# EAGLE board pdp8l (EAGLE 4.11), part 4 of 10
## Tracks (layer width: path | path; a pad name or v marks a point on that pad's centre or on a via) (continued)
INT_SKIP_EN\  (via drill 0.61) (continued)
  Top 0.203: v283.26,84.38 282.85,84.78 282.85,116.08 282.45,116.48 282.45,154.69 286.51,158.75 286.51,160.78 286.11,161.19 286.11,170.94 v286.51,171.35 | v270.26,187.6 270.26,205.08 271.07,205.89 v271.07,218.49 | v281.63,222.96 281.63,224.99 A14.T2
  Route2 0.203: v329.18,256.29 328.78,256.29 316.59,244.09 316.59,243.69 315.37,242.47 314.96,242.47 297.49,224.99 v297.49,224.59
  Route15 0.203: v270.26,187.6 v286.51,171.35 | v329.18,256.29 v356.41,229.06
  Bottom 0.203: v283.26,84.38 287.73,84.38 290.98,81.13 317.81,81.13 318.62,81.94 C11.V2 | v271.07,218.49 276.35,223.77 280.82,223.77 v281.63,222.96 | v356.41,229.06 359.66,229.06 A08.S2 | v297.49,224.59 297.08,224.18 284.07,224.18 283.26,224.99 281.63,224.99 A14.T2
INT_STROBE  (via drill 0.61)
  Top 0.203: v432.41,85.19 432,84.78 432,81.94 432.82,81.13 432.82,69.75 434.85,67.72 434.85,56.74 432,53.9 432,49.84 435.25,46.58 435.25,38.05 437.69,35.61 437.69,27.48 439.32,25.86 D02.R1
  Route2 0.203: C14.P2 284.48,99.01 284.48,100.63 293.01,109.17 294.64,109.17 296.27,110.79 C13.K2 297.49,111.61 297.49,116.08 298.3,116.89 298.3,120.95 302.36,125.02 306.43,125.02 319.84,138.43 319.84,138.84 328.78,147.78 328.78,148.59 333.25,153.06 333.25,153.47 347.88,168.1 v347.88,168.5
  Route15 0.203: v332.44,183.95 v347.88,168.5 371.04,145.34 373.48,145.34 397.87,120.95 401.12,120.95 C05.F1 401.93,120.14 403.15,118.92 403.15,115.67 404.37,114.45 404.77,114.45 432.41,86.82 v432.41,85.19
  Bottom 0.203: v332.44,183.95 329.18,183.95 B11.H1
INT_SYNC  (via drill 0.61)
  Top 0.203: v296.67,127.86 296.67,124.61 C13.E2
  Route2 0.203: v296.67,127.86 304.39,135.59 304.39,136.4 316.18,148.18 316.18,149 323.09,155.91 323.09,157.94 323.49,158.34 323.49,163.63 323.9,164.03 323.9,164.85 326.75,167.69 326.75,169.72 327.96,170.94 B11.M1
IO_ENABLE  (via drill 0.61)
  Top 0.203: v335.69,55.93 336.09,56.34 336.09,81.13 335.69,81.53 v335.69,83.57 | v304.8,177.04 304.39,176.63 304.39,172.97 303.58,172.16 B13.M1 | AB07.BL2 369.82,175.41 368.61,176.63 368.61,220.12 368.2,220.52 368.2,226.62 366.98,227.84 A08.S1 366.57,229.06 366.57,232.31 365.35,233.53 365.35,248.56 363.73,248.56 362.1,250.19 v362.1,281.89 | v303.99,281.48 298.3,275.79 298.3,251.41 294.23,251.41 A13.J2 | v284.48,115.27 282.85,116.89 282.85,148.59 v288.54,154.28
  Route2 0.203: v288.54,154.28 288.54,154.69 301.55,167.69 301.55,169.72 302.77,170.94 B13.M1
  Route15 0.203: v335.69,55.93 344.22,47.4 344.22,44.96 D09.J2 | v34.14,274.98 23.16,264.01 21.13,264.01 A35.D1 | v284.48,115.27 302.77,96.98 302.77,94.54 309.27,88.04 309.27,86.41 C12.U2
  Bottom 0.203: v335.69,83.57 334.87,84.38 315.37,84.38 314.55,85.19 310.08,85.19 C12.U2 | 419.4,175.82 409.25,175.82 408.43,175.01 AB04.BL2 407.21,174.6 405.18,174.6 403.96,175.82 396.65,175.82 395.83,175.01 AB05.BL2 394.61,175.01 390.55,175.01 389.74,175.82 384.05,175.82 383.24,175.01 AB06.BL2 382.02,175.01 377.95,175.01 377.14,175.82 373.89,175.82 373.07,175.01 370.64,175.01 AB07.BL2 369.42,175.01 365.35,175.01 361.29,179.07 345.44,179.07 343,176.63 305.21,176.63 v304.8,177.04 | 419.4,175.82 420.22,175.01 AB03.BL2 | 419.4,175.82 432,175.82 432.82,175.01 AB02.BL2 | 304.8,282.3 v303.99,281.48 | 304.8,282.3 361.7,282.3 v362.1,281.89 | v34.14,274.98 36.98,277.83 147.52,277.83 149.56,279.86 167.84,279.86 169.06,281.08 238.96,281.08 239.78,280.26 269.85,280.26 271.07,281.48 275.54,281.48 275.95,281.08 287.32,281.08 288.54,282.3 304.8,282.3
IO_END\  (via drill 0.61)
  Top 0.203: C05.K1 404.37,111.61 403.56,112.42 403.56,118.52 403.96,118.92 403.96,122.99 404.37,123.39 C05.E1 | v436.88,31.95 436.88,29.11 D02.P2
  Route2 0.203: v436.88,31.95 436.88,33.17 440.94,37.24 440.94,49.02 v452.73,60.81
  Route15 0.203: v452.73,60.81 452.32,60.4 451.51,61.21 451.51,62.43 451.1,62.84 451.1,66.9 449.07,68.94 448.67,68.94 445.01,72.59 445.01,81.53 422.66,103.89 422.66,104.29 422.25,104.7 421.44,104.7 406.81,119.33 406.81,121.77 405.18,123.39 C05.E1
IO_ON  (via drill 0.61)
  Top 0.203: D04.N2 407.62,32.36 406.81,33.17 406.81,42.93 407.62,43.74 D04.J2 407.62,44.96 407.62,47.4 406.81,48.21 406.81,55.12 | 406.81,55.12 408.03,56.34 D04.D2 | v403.56,107.95 406.4,107.95 406.4,73.41 405.99,73 405.99,72.19 407.21,70.97 407.21,66.09 406.81,65.68 406.81,55.12
  Bottom 0.203: v403.56,107.95 402.34,106.73 390.96,106.73 389.74,107.95 C06.L1
IO_PC_ENABLE\  (via drill 0.61)
  Route2 0.203: v154.84,129.9 162.97,138.02 165.41,138.02 v249.12,221.74
  Bottom 0.203: v154.84,129.9 153.62,128.68 111.35,128.68 110.13,127.46 C28.D1 | v249.12,221.74 251.16,223.77 265.38,223.77 265.79,224.18 281.63,224.18 283.26,222.56 283.67,222.56 A14.U2 284.89,222.15 286.11,220.93 358.44,220.93 359.66,222.15 A08.U2
IO_RECYCLE\
  Top 0.203: C05.P1 404.77,99.01 404.77,102.67 405.99,103.89 405.99,107.14 405.59,107.54 404.37,107.54 403.56,106.73 398.68,106.73 398.68,110.39 C05.K2
IO_ROT\  (via drill 0.61)
  Top 0.203: v371.86,40.08 377.95,40.08 377.95,63.25 381.2,66.5 381.2,105.92 382.42,107.14 C06.L2 382.42,108.76 381.2,109.98 381.2,121.36 381.61,121.77 381.61,125.42 382.42,126.24 C06.D2
  Route2 0.203: C06.B1 388.52,132.74 388.52,131.12 386.08,128.68 384.45,128.68 383.24,127.46 C06.D2
  Bottom 0.203: v371.86,40.08 363.73,40.08 363.73,43.74 D08.J1
IO_SKIP  (via drill 0.61)
  Route2 0.203: v74.78,276.2 46.74,248.16 46.74,244.91 A33.L1
  Route15 0.203: v233.27,277.01 245.06,265.23 271.07,265.23 286.92,249.38 295.86,249.38 297.08,248.16 A13.K2
  Bottom 0.203: v74.78,276.2 154.03,276.2 155.65,277.83 173.94,277.83 175.16,279.04 221.49,279.04 222.71,277.83 232.46,277.83 v233.27,277.01
IO_START\  (via drill 0.61)
  Top 0.203: 396.65,109.58 396.65,96.57 v397.46,95.76 | 396.65,109.58 396.65,114.86 395.43,116.08 395.43,120.14 C05.F2 | 396.65,109.58 v396.24,109.58
  Bottom 0.203: v397.46,95.76 401.12,95.76 C05.R1 | v396.24,109.58 415.75,109.58 416.97,110.79 C04.K1
IO_STROBE  (via drill 0.61)
  Top 0.203: v306.83,85.19 306.83,88.44 C12.T2 | v336.5,81.94 338.94,79.5 v338.94,73.41 | v391.36,107.54 390.96,107.95 390.96,112.01 391.77,112.83 391.77,116.89 C06.H1 | v367.39,83.57 367.79,83.16 367.79,69.75 365.35,67.31 365.35,53.09 363.73,51.46 D08.F1
  Route2 0.203: v278.79,145.75 279.6,146.56 279.6,149.81 289.76,159.97 289.76,162 299.52,171.75 299.52,174.19 B13.L1 | v391.36,107.54 v367.39,83.57
  Route15 0.203: D08.F1 362.92,51.05 361.29,52.68 359.66,52.68 v338.94,73.41 338.53,73.41 338.12,73.81 336.91,73.81 332.44,78.28 332.44,79.1 323.9,87.63 323.9,90.88 323.49,91.29 323.49,92.51 322.68,93.32 322.27,93.32 320.24,95.35 320.24,96.16 312.93,103.48 312.93,105.1 304.39,113.64 303.99,113.64 301.14,116.48 300.33,116.48 294.23,122.58 289.76,122.58 288.54,123.8 288.54,127.86 284.48,131.93 284.48,132.74 278.79,138.43 v278.79,145.75
  Bottom 0.203: C06.H1 392.58,117.3 397.87,117.3 C05.H2 399.08,117.3 404.37,117.3 C05.H1 | v306.83,85.19 307.64,84.38 314.55,84.38 314.96,83.97 334.06,83.97 336.09,81.94 v336.5,81.94
IOP1  (via drill 0.61)
  Top 0.203: v66.65,225.4 66.65,229.87 65.43,231.09 AB31.AR2 | v428.35,49.84 428.75,49.43 v428.75,13.26 | v81.69,12.85 76.81,17.73 67.06,17.73 67.06,25.45 69.49,27.89 69.49,46.18 68.68,46.99 D31.H2 | v183.69,106.73 183.69,18.95 181.25,16.51 v181.25,5.54 | v204.42,147.37 206.45,145.34 206.45,120.95 215.8,111.61 215.8,109.17 v215.8,108.76
  Route2 0.203: v215.8,108.76 241.81,134.77 241.81,135.59 242.21,135.99 242.62,135.99 249.53,142.9 254,142.9 260.1,149 260.1,150.22 271.88,162 271.88,163.63 272.69,164.44 272.69,169.72 273.1,170.13 273.1,172.16 273.51,172.57 273.51,175.41 275.95,177.85 275.95,179.07 277.57,180.7 277.57,183.54 B15.H1
  Route15 0.203: D32.D2 52.83,56.74 56.9,56.74 64.21,49.43 65.84,49.43 67.46,47.8 D31.H2 | v131.67,218.08 131.67,217.68 144.68,204.67 145.09,204.67 173.13,176.63 173.13,176.22 173.53,175.82 175.97,175.82 v204.42,147.37
  Bottom 0.203: v66.65,225.4 67.87,224.18 74.78,224.18 76.4,222.56 80.47,222.56 AB30.AU2 81.69,222.15 83.31,220.52 129.24,220.52 v131.67,218.08 | v428.35,49.84 429.97,51.46 432.41,51.46 432.82,51.05 D02.F2 | v428.75,13.26 428.75,10.01 386.49,10.01 384.45,7.98 307.64,7.98 306.02,6.35 293.01,6.35 291.8,5.13 262.53,5.13 260.91,6.76 247.09,6.76 246.28,5.94 212.95,5.94 212.55,5.54 v181.25,5.54 89,5.54 v81.69,12.85 | v215.8,108.76 215.39,109.17 188.57,109.17 186.13,106.73 v183.69,106.73
IOP1\  (via drill 0.61)
  Top 0.203: v370.64,234.75 371.04,234.34 371.04,145.75 | 371.04,145.75 371.04,84.38 372.67,82.75 372.67,70.97 v372.26,70.56 | v406.4,70.56 v406.4,47.4 | v434.85,48.21 434.85,52.27 436.07,53.49 D02.E2 | v95.5,125.83 95.5,119.74 93.88,118.11 C29.H2 | 371.04,145.75 v368.61,145.75
  Route2 0.203: v274.32,129.08 273.91,129.49 288.54,144.12 290.58,144.12 299.92,153.47 v299.92,153.87
  Route15 0.203: v299.92,153.87 299.92,153.47 305.61,147.78 307.24,147.78 v308.86,146.15
  Bottom 0.203: C29.J2 91.03,114.86 93.07,116.89 93.47,116.89 C29.H2 | v370.64,234.75 367.39,234.75 A08.P1 | v372.26,70.56 372.67,70.16 405.99,70.16 v406.4,70.56 | v406.4,47.4 410.46,47.4 D04.H2 411.68,46.99 412.5,46.18 432.82,46.18 v434.85,48.21 | v95.5,125.83 154.43,125.83 154.84,125.42 262.13,125.42 262.53,125.02 264.57,125.02 268.22,128.68 273.91,128.68 v274.32,129.08 | v308.86,146.15 321.46,146.15 322.68,144.93 349.1,144.93 349.91,145.75 363.32,145.75 363.73,145.34 368.2,145.34 v368.61,145.75
IOP2  (via drill 0.61)
  Top 0.203: v71.53,235.97 71.53,232.31 AB31.AR1 | v168.66,236.78 171.09,236.78 171.09,88.85 165,82.75 165,46.58 v164.59,46.18
  Route2 0.203: D32.J2 52.83,44.96 54.86,44.96 63.4,53.49 63.4,54.71 65.02,56.34 D31.D2
  Route15 0.203: AB30.AV2 78.44,219.3 81.69,219.3 83.72,221.34 75.18,229.87 73.56,229.87 71.93,231.5 AB31.AR1
  Bottom 0.203: A36.M2 5.28,240.84 6.5,239.62 48.36,239.62 51.61,236.37 71.12,236.37 v71.53,235.97 71.93,235.97 72.75,236.78 v168.66,236.78 | 164.59,45.77 115.42,45.77 115.01,46.18 84.12,46.18 83.72,45.77 53.65,45.77 52.83,44.96 D32.J2 | 164.59,45.77 230.84,45.77 233.68,42.93 237.34,42.93 240.18,45.77 313.33,45.77 313.74,45.36 315.37,45.36 315.77,45.77 325.93,45.77 328.78,42.93 358.44,42.93 361.29,45.77 395.83,45.77 396.65,44.96 399.9,44.96 400.71,45.77 432,45.77 432.82,44.96 D02.J2 | 164.59,45.77 v164.59,46.18
IOP2\  (via drill 0.61)
  Top 0.203: C29.N2 91.03,101.04 91.03,100.63 93.07,98.6 C29.P2 93.88,97.79 95.5,96.16 95.5,79.1 97.94,76.66 97.94,66.5 91.85,60.4 91.85,36.42 91.03,35.61 91.03,33.17 92.25,31.95 v92.25,17.73 | v364.13,233.53 364.13,237.59 A08.N1 | v371.86,233.53 371.45,233.12 371.45,89.26 374.29,86.41 v374.29,78.69 | v390.14,78.69 390.55,78.28 390.55,38.46 v390.96,38.05 | v436.88,37.64 436.88,38.86 437.69,39.68 437.69,46.18 436.88,46.99 D02.H2
  Route2 0.203: v341.38,13.66 v363.73,36.02
  Bottom 0.203: v371.86,233.53 v364.13,233.53 | v374.29,78.69 374.7,79.1 389.74,79.1 v390.14,78.69 | 392.18,36.83 v390.96,38.05 | 392.18,36.83 407.21,36.83 408.84,35.2 410.46,35.2 D04.M2 411.68,35.2 413.31,36.83 436.07,36.83 v436.88,37.64 | v92.25,17.73 92.66,17.32 94.28,17.32 102.82,8.79 208.48,8.79 209.3,7.98 237.34,7.98 239.78,10.41 301.95,10.41 305.61,14.07 340.97,14.07 v341.38,13.66 | v363.73,36.02 364.54,36.83 392.18,36.83
IOP4  (via drill 0.61)
  Top 0.203: v77.22,105.92 76,104.7 76,93.32 75.18,92.51 C31.S1 | v64.21,179.48 63.8,179.88 63.8,232.31 64.62,233.12 67.06,233.12 67.06,232.31 67.46,231.9 68.68,231.9 68.68,234.34 AB31.AP2 | v54.05,179.48 54.05,142.49 53.65,142.09 53.65,109.98 52.43,108.76 C32.L2 | v438.1,142.9 v438.1,38.86 | v277.98,142.9 276.35,144.53 v276.35,145.75 276.35,195.33 275.13,196.54 275.13,199.39 B15.B1
  Route2 0.203: B15.A1 277.57,202.64 277.17,202.64 275.13,200.61 B15.B1 | v218.64,86.82 218.64,87.22 273.91,142.49 273.91,143.31 v276.35,145.75
  Bottom 0.203: v77.22,105.92 54.46,105.92 52.83,107.54 C32.L2 | AB30.BK1 86.56,177.85 84.94,179.48 v64.21,179.48 63.8,179.48 v54.05,179.48 | v438.1,38.86 434.44,38.86 434.04,38.46 D02.L2 | v438.1,142.9 437.69,142.49 278.38,142.49 v277.98,142.9 | v218.64,86.82 218.24,87.22 205.64,87.22 202.79,84.38 162.15,84.38 158.9,87.63 108.92,87.63 106.48,90.07 76.81,90.07 75.18,91.69 C31.S1
IOP4\  (via drill 0.61)
  Top 0.203: C29.V2 91.03,83.16 93.07,85.19 C29.U2 | v372.26,231.9 371.86,231.5 371.86,89.66 374.7,86.82 374.7,79.5 375.11,79.1 375.11,60.81 v376.73,59.18 | v401.12,9.2 406.81,14.88 410.46,14.88 410.46,14.48 412.5,14.48 412.5,20.98 411.68,21.79 D04.S2
  Route2 0.203: D02.K2 436.07,40.89 432.82,40.89 420.22,28.3 419.4,28.3 415.34,24.23 413.31,24.23 411.68,22.61 D04.S2
  Route15 0.203: v372.26,231.9 367.39,236.78 367.39,240.84 A08.M1 | v376.73,59.18 405.99,29.92 405.99,29.11 409.25,25.86 409.25,24.64 410.87,23.01 D04.S2 | v184.51,4.32 176.38,12.45 176.38,13.66 150.37,39.68 143.05,39.68 121.51,61.21 120.29,61.21 111.76,69.75 107.7,69.75 106.88,70.56 106.07,70.56 94.69,81.94 91.03,81.94 C29.V2
  Bottom 0.203: v184.51,4.32 185.72,3.1 293.83,3.1 294.64,3.91 295.86,3.91 296.27,4.32 297.49,4.32 299.92,1.88 344.63,1.88 346.25,3.5 395.43,3.5 v401.12,9.2
IOP_A  (via drill 0.61)
  Top 0.203: v412.9,105.1 412.9,100.23 413.31,99.82 413.31,96.16 412.5,95.35 v412.5,78.69 | v408.43,77.06 407.62,76.25 v407.62,65.28 | v412.09,65.28 412.5,64.87 412.5,58.78 411.28,57.56 411.28,54.71 D04.E2
  Route15 0.203: v412.9,105.1 394.61,123.39 392.58,123.39 C06.E1
  Bottom 0.203: v412.5,78.69 412.09,78.28 411.68,78.28 410.46,77.06 v408.43,77.06 | v407.62,65.28 v412.09,65.28
IOP_A\  (via drill 0.61)
  Top 0.203: v389.74,104.7 390.14,105.1 390.14,116.48 388.93,117.7 388.93,120.14 C06.F1
  Route15 0.203: v389.74,104.7 386.49,104.7 C06.M2
IOP_B  (via drill 0.61)
  Top 0.203: v410.46,78.28 410.06,77.88 410.06,69.75 412.9,66.9 412.9,58.37 412.5,57.96 412.5,42.52 411.68,41.71 D04.K2
  Route15 0.203: v401.12,78.69 386.49,93.32 384.86,93.32 383.24,94.94 C06.R2
  Bottom 0.203: v410.46,78.28 410.06,78.69 v401.12,78.69
IOP_B\
  Top 0.203: C06.P2 385.27,99.01 384.45,99.82 384.45,122.58 385.27,123.39 C06.E2
IOP_C  (via drill 0.61)
  Top 0.203: v390.96,115.27 390.96,128.68 391.77,129.49 C06.C1 | v386.89,56.74 386.89,81.53 v383.64,84.78
  Route2 0.203: v367.79,101.45 372.67,106.32 373.07,106.32 373.48,106.73 373.48,107.95 v379.17,113.64
  Route15 0.203: v386.89,56.74 396.65,46.99 396.65,45.77 410.87,31.55 410.87,29.11 D04.P2 | v383.64,84.78 371.45,96.98 371.45,97.79 v367.79,101.45
  Bottom 0.203: 390.96,115.67 400.3,115.67 401.12,114.86 C05.J1 | 390.96,115.67 384.45,115.67 383.24,114.45 C06.J2 382.02,114.05 379.58,114.05 v379.17,113.64 | 390.96,115.67 v390.96,115.27
IOP_C\
  Bottom 0.203: C06.H2 386.49,117.3 387.71,116.08 401.93,116.08 403.15,114.86 403.15,112.83 400.3,112.83 399.08,114.05 395.83,114.05 C05.J2
IOT  (via drill 0.61)
  Top 0.203: v377.95,99.82 377.55,99.42 377.55,81.94 377.14,81.53 377.14,80.31 378.36,80.31 378.76,80.72 378.76,84.78 379.17,85.19 C07.U1
  Route2 0.203: v377.95,99.82 397.05,118.92 397.05,122.58 397.87,123.39 C05.E2
  Route15 0.203: v313.33,166.47 316.59,166.47 333.25,149.81 333.25,148.18 356.82,124.61 357.63,124.61 369.42,112.83 371.86,112.83 372.26,112.42 373.48,112.42 374.29,111.61 374.29,105.51 377.55,102.26 377.55,100.63 377.95,100.23 v377.95,99.82
  Bottom 0.203: v313.33,166.47 308.86,166.47 308.46,166.06 304.39,166.06 303.99,166.47 299.92,166.47 295.86,170.54 291.39,170.54 290.98,170.94 B14.M1
IOT\  (via drill 0.61)
  Top 0.203: v346.25,91.29 346.25,83.97 v346.66,83.57 | v399.9,119.74 399.9,131.52 401.12,132.74 C05.B1 | v376.73,116.89 375.11,115.27 375.11,92.91 375.51,92.51 375.51,90.07 375.11,89.66 375.11,83.97 375.92,83.16 C07.V1
  Bottom 0.203: v346.25,91.29 343.81,91.29 343,90.47 334.47,90.47 333.65,91.29 329.59,91.29 329.18,91.69 C11.S1 | v346.66,83.57 349.1,81.13 370.64,81.13 371.04,81.53 371.04,82.35 375.51,82.35 C07.V1 | v399.9,119.74 399.08,118.92 397.05,118.92 396.65,118.52 392.99,118.52 392.58,118.92 391.36,118.92 390.96,118.52 390.96,116.89 388.52,116.89 386.49,118.92 378.76,118.92 v376.73,116.89
IR0  (via drill 0.61)
  Top 0.203: C09.P1 353.57,99.01 353.16,99.42 353.16,103.89 352.75,104.29 352.75,105.92 353.97,107.14 353.97,110.39 C09.K1 353.57,111.61 352.75,112.42 v352.75,119.33 | v343,121.77 343,134.77 341.78,135.99 C10.A1 | v305.21,79.1 305.61,78.69 305.61,69.75 305.21,69.34 305.21,62.84 306.43,61.62 306.43,57.96 D12.D2
  Route2 0.203: v305.21,79.1 320.24,94.13 320.24,95.35 321.06,96.16 321.87,96.16 326.75,101.04 326.75,102.67 328.37,104.29 C11.M1 328.78,105.51 330.4,107.14 330.4,108.76 337.72,116.08 341.78,116.08 343,117.3 343,121.36 v343,121.77
  Bottom 0.203: 343,119.33 v352.75,119.33 362.1,119.33 362.92,120.14 C08.F1 | 343,119.33 340.16,119.33 338.94,120.55 C10.F1 | v343,121.77 343,119.33
IR0\  (via drill 0.61)
  Top 0.203: C09.A1 353.57,135.99 353.57,131.52 352.75,130.71 352.75,125.83 353.97,124.61 C09.E1 | v345.85,96.16 345.85,103.48 343,106.32 343,109.98 344.22,111.2 344.22,113.64 C09.J2 345.03,114.86 345.03,117.3 345.85,118.11 345.85,125.02 344.63,126.24 C09.D2
  Bottom 0.203: C09.D2 345.03,126.64 346.25,125.42 352.35,125.42 353.57,124.21 C09.E1 354.79,124.21 357.23,124.21 358.04,125.02 365.35,125.02 366.17,124.21 C08.E1 | C15.R1 275.13,95.76 275.95,96.57 345.44,96.57 v345.85,96.16 345.85,96.57 364.13,96.57 364.54,96.16 366.17,96.16 366.57,96.57 379.58,96.57 380.8,97.79 382.42,97.79 383.64,96.57 434.04,96.57 436.88,93.73 444.19,93.73 445.41,94.94 C01.R2
IR1  (via drill 0.61)
  Top 0.203: v346.66,116.08 346.66,112.01 347.07,111.61 C09.K2 | v311.3,66.5 311.3,60 309.68,58.37 309.68,54.71 D12.E2 | v324.31,68.53 323.9,68.94 323.9,96.98 325.12,98.2 325.12,101.04 C11.N1
  Route2 0.203: C10.H1 340.56,117.3 338.12,117.3 330,109.17 330,108.36 325.53,103.89 325.53,102.26 C11.N1
  Route15 0.203: C10.B1 338.94,133.15 340.56,133.15 349.1,124.61 349.1,122.99 350.72,121.36 C09.F1
  Bottom 0.203: C10.H1 341.78,116.89 342.6,116.08 v346.66,116.08 358.44,116.08 359.66,117.3 C08.H2 360.88,116.89 364.95,116.89 364.95,121.36 364.13,122.17 352.75,122.17 351.54,120.95 C09.F1 | v311.3,66.5 313.33,68.53 v324.31,68.53
IR1\  (via drill 0.61)
  Top 0.203: C09.B1 350.32,132.74 349.5,131.93 349.5,126.24 347.88,124.61 C09.E2 348.29,123.39 349.5,122.17 349.5,110.79 350.72,109.58 350.72,108.76 C09.L1 350.72,107.14 350.72,105.92 349.5,104.7 349.5,96.57 350.32,95.76 C09.R1 351.13,94.54 352.75,92.91 v352.75,79.1
  Route2 0.203: C08.J2 356.41,114.05 355.19,114.05 352.75,111.61 352.75,110.39 351.13,108.76 C09.L1
  Bottom 0.203: v352.75,79.1 353.16,79.5 414.93,79.5 415.75,78.69 441.76,78.69 445.41,82.35 C01.V2
IR2  (via drill 0.61)
  Top 0.203: 355.19,109.17 355.19,128.68 354.38,129.49 C09.C1 | 355.19,109.17 355.19,93.32 354.38,92.51 C09.S1 | 355.19,109.17 v354.79,109.17
  Bottom 0.203: 345.03,109.17 345.03,108.76 344.63,108.76 C09.L2 | 345.03,109.17 345.03,110.79 341.78,114.05 338.94,114.05 C10.J1 | 345.03,109.17 v354.79,109.17 362.1,109.17 362.92,108.36 C08.L1 | C10.C1 341.78,129.49 342.19,129.08 346.66,129.08 347.07,128.68 352.75,128.68 353.57,129.49 C09.C1
IR2\  (via drill 0.61)
  Top 0.203: v380.39,68.53 380.8,68.94 v380.8,106.73 | v366.57,106.73 366.57,105.51 C08.M1
  Route15 0.203: C08.M1 366.17,105.1 364.13,105.1 358.85,110.39 358.85,114.45 357.63,115.67 356.41,115.67 354.79,117.3 C09.H1 | v344.63,118.52 344.63,120.14 C09.F2 | v351.94,106.73 353.57,105.1 C09.M1
  Bottom 0.203: C11.P1 329.18,99.01 330.4,100.23 333.25,100.23 336.09,103.07 349.91,103.07 351.54,104.7 353.57,104.7 C09.M1 | v380.39,68.53 380.8,68.94 416.56,68.94 416.97,68.53 450.7,68.53 450.7,59.59 450.29,59.18 448.26,59.18 446.63,57.56 D01.D2 | v380.8,106.73 380.39,106.32 366.98,106.32 v366.57,106.73 366.57,106.32 352.35,106.32 v351.94,106.73 | v344.63,118.52 345.03,118.92 351.94,118.92 352.75,118.11 353.57,118.11 C09.H1
ISZ  (via drill 0.61)
  Top 0.203: v367.79,132.74 365.35,135.18 365.35,138.02 367.79,140.46 v367.79,149.81
  Route2 0.203: v325.93,196.14 327.96,198.17 332.03,198.17 333.25,199.39 333.25,207.11 339.34,213.21 339.34,214.02 340.16,214.83 340.97,214.83 342.6,216.46 342.6,217.68 v341.78,218.49
  Route15 0.203: v367.79,132.74 382.02,118.52 382.02,116.48 379.98,114.45 379.98,111.61 C07.K1 | v367.79,149.81 367.39,149.81 348.69,168.5 348.69,168.91 347.47,170.13 347.07,170.13 333.25,183.95 333.25,184.35 331.62,185.98 331.22,185.98 330.4,186.79 330.4,191.67 v325.93,196.14 | v341.78,218.49 341.78,219.71 308.05,253.44 308.05,255.47 306.83,256.69 A12.F2
  Bottom 0.203: A13.H2 297.49,254.25 299.11,255.88 301.95,255.88 303.17,257.1 305.61,257.1 A12.F2
ISZ\
  Bottom 0.203: C09.J1 351.54,114.05 352.75,112.83 371.04,112.83 372.26,114.05 375.51,114.05 C07.J1
JMP  (via drill 0.61)
  Top 0.203: v300.74,137.62 300.74,134.37 300.33,133.96 C13.B1 | v374.7,138.43 v374.7,92.1 | v288.95,219.3 288.54,218.9 288.54,207.92 287.73,207.11 v287.73,204.27
  Route2 0.203: A10.D1 337.72,262.79 336.5,261.57 334.06,261.57 329.59,257.1 328.78,257.1 316.59,244.91 315.37,244.91 314.96,244.5 314.96,244.09 306.83,235.97 305.21,235.97 304.39,235.15 303.99,235.15 A13.P1 302.77,234.34 300.33,234.34 295.45,229.46 295.45,225.4 289.36,219.3 v288.95,219.3 | v299.52,203.45 299.52,203.05 287.32,190.86 287.32,189.64 276.35,178.66 276.35,174.19 v273.91,171.75
  Route15 0.203: v273.91,171.75 273.91,170.94 282.45,162.41 282.45,158.34 282.85,157.94 282.85,155.91 290.17,148.59 290.17,145.34 298.3,137.21 298.3,135.18 299.52,133.96 C13.B1
  Bottom 0.203: v300.74,137.62 301.55,138.43 319.43,138.43 320.24,139.24 336.91,139.24 337.72,138.43 345.85,138.43 347.07,139.65 362.92,139.65 364.13,138.43 v374.7,138.43 | v374.7,92.1 378.76,92.1 C07.S1 | v287.73,204.27 288.14,204.67 298.3,204.67 v299.52,203.45
JMP\  (via drill 0.61)
  Top 0.203: v317.81,94.13 317.81,56.34 316.18,54.71 D12.E1 | v322.68,94.13 322.68,96.57 323.9,97.79 323.9,113.23 324.71,114.05 C11.J1 325.53,114.86 325.53,117.7 326.75,118.92 326.75,121.36 326.34,121.77 326.34,125.02 326.75,125.42 326.75,133.96 324.31,136.4 324.31,189.23 v324.71,189.64 | v336.5,235.15 336.09,235.15 336.09,220.12 334.47,218.49 334.47,204.67 333.25,203.45 v333.25,198.17
  Route2 0.203: v333.25,198.17 v324.71,189.64
  Route15 0.203: v336.5,235.15 340.56,235.15 A10.P1 | v350.32,92.51 353.57,89.26 353.57,86.41 C09.U1
  Bottom 0.203: C15.R2 269.04,94.94 270.26,93.73 317.4,93.73 v317.81,94.13 317.81,93.73 322.27,93.73 v322.68,94.13 322.68,93.73 349.1,93.73 | 349.1,93.73 v350.32,92.51 | 349.1,93.73 370.23,93.73 371.45,94.94 375.51,94.94 C07.R1
JMP_DIRECT\  (via drill 0.61)
  Top 0.203: 345.85,243.28 345.03,244.09 A09.L2 | 345.85,243.28 347.07,243.28 347.07,247.34 A09.K2 | v304.8,166.88 304.8,125.83 303.58,124.61 C13.E1 | v345.85,222.56 345.85,243.28
  Route2 0.203: v345.85,222.56 343,219.71 343,215.24 340.97,213.21 340.97,209.14 345.03,205.08 345.44,205.08 346.25,204.27 336.09,194.11 335.69,194.11 335.28,193.7 335.28,192.89 324.31,181.91 324.31,177.44 v315.37,168.5
  Bottom 0.203: v304.8,166.88 310.9,166.88 312.12,168.1 B12.N1 313.33,168.5 v315.37,168.5
JMS  (via drill 0.61)
  Top 0.203: v322.27,81.53 322.27,85.19 C11.U2 | v377.95,81.13 377.95,96.57 379.17,97.79 C07.P1 379.17,99.01 378.76,99.42 378.76,103.48 377.95,104.29 377.95,107.14 378.76,107.95 v378.76,109.58 | B10.H2 335.28,184.76 336.09,185.57 336.09,192.07 335.28,192.89 335.28,193.7 336.91,195.33 v336.91,232.72 337.31,232.72 337.31,235.56 336.09,236.78 336.09,255.07 v335.69,255.47 | v377.14,110.39 377.55,110.79 377.55,144.12 v375.92,145.75
  Route2 0.203: v335.69,255.47 334.47,256.69 332.44,256.69 A10.F2 | v378.76,109.58 377.55,110.79 v377.14,110.39
  Route15 0.203: v318.62,268.07 319.02,268.07 327.96,259.13 329.59,259.13 331.22,257.5 A10.F2 | v375.92,145.75 339.34,182.32 337.72,182.32 335.69,184.35 B10.H2
  Bottom 0.203: v322.27,81.53 322.68,81.13 340.16,81.13 343,83.97 345.03,83.97 348.29,80.72 377.55,80.72 v377.95,81.13 | v336.91,232.72 336.09,233.53 319.84,233.53 318.62,234.75 316.59,234.75 A12.P1 | v318.62,268.07 306.02,268.07 305.21,268.88 301.55,268.88 300.74,269.7 A13.B1
JMS\  (via drill 0.61)
  Route2 0.203: v271.48,103.07 271.48,99.01 C15.P2
  Bottom 0.203: v271.48,103.07 271.88,103.48 301.55,103.48 303.58,101.45 303.58,100.23 324.71,100.23 327.96,96.98 337.72,96.98 340.56,99.82 351.13,99.82 351.54,99.42 352.35,99.42 352.75,99.82 352.75,100.23 | 352.75,100.23 352.75,101.04 351.13,101.04 C09.N1 | 352.75,100.23 374.29,100.23 375.51,101.45 C07.N1
KCC\  (via drill 0.61)
  Top 0.203: v50.39,122.58 50.39,84.78 52.02,83.16 C32.V2
  Bottom 0.203: v50.39,122.58 51.21,123.39 54.86,123.39 C32.E2
KEY_CONT  (via drill 0.61)
  Top 0.203: v428.75,94.94 428.75,52.68 v430.78,50.65
  Bottom 0.203: v428.75,94.94 432.82,94.94 C02.R2 | v430.78,50.65 432.41,49.02 440.94,49.02 442.16,47.8 D02.H1
KEY_CONT\  (via drill 0.61)
  Top 0.203: v441.35,32.36 441.35,49.02 440.13,50.24 D02.F1 | v365.35,143.31 365.35,201.83 366.17,202.64 B08.A1 | v392.18,143.31 393.8,141.68 393.8,96.98 395.02,95.76 C05.R2 395.43,94.54 395.43,90.07 v399.08,90.07 | v427.94,52.68 428.35,53.09 428.35,89.66 v427.53,90.47
  Bottom 0.203: D01.S1 455.57,23.01 455.57,24.23 453.14,26.67 451.51,26.67 449.88,28.3 D01.P2 448.67,29.11 444.6,29.11 v441.35,32.36 | v392.18,143.31 v365.35,143.31 | v427.94,52.68 438.1,52.68 439.32,51.46 D02.F1 | v427.53,90.47 427.13,90.07 v399.08,90.07
KEY_DP  (via drill 0.61)
  Top 0.203: A10.S2 334.47,229.06 334.47,234.34 A10.P2 | v314.55,79.5 314.55,92.51 314.96,92.91 314.96,96.98 315.77,97.79 C12.P1 | v432,79.5 432,59.18 433.22,57.96 D02.D2
  Route2 0.203: v448.67,96.57 448.67,95.76 432.41,79.5 v432,79.5
  Route15 0.203: A10.R2 332.03,231.09 332.44,231.09 334.47,229.06 A10.S2 335.69,228.65 338.94,228.65 340.97,230.68 342.6,229.06 342.6,223.77 343,223.37 343,218.08 344.63,216.46 351.13,216.46 363.73,203.86 363.73,201.83 399.9,165.66 399.9,154.69 400.3,154.28 400.3,152.65 403.15,149.81 403.15,146.56 438.91,110.79 438.91,110.39 443.38,105.92 443.79,105.92 447.45,102.26 447.45,97.79 v448.67,96.57
  Bottom 0.203: v314.55,79.5 314.96,79.91 418.59,79.91 419,79.5 v432,79.5
KEY_DP\  (via drill 0.61)
  Top 0.203: v431.19,115.27 431.6,114.86 431.6,82.75 429.56,80.72 v429.56,72.19 | v446.63,58.78 447.45,57.96 447.45,14.07 446.63,13.26 D01.V2
  Route2 0.203: v431.19,115.27 439.73,123.8 439.73,126.24 C02.D1
  Route15 0.203: v429.56,72.19 429.56,71.78 439.32,62.03 440.54,62.03 442.16,60.4 D02.C1
  Bottom 0.203: v446.63,58.78 445.41,60 443.38,60 D02.C1
KEY_EX+DP  (via drill 0.61)
  Top 0.203: D02.D1 439.73,57.96 438.51,59.18 438.51,115.67 439.73,116.89 439.73,120.14 C02.F1 | v310.49,244.5 310.9,244.09 v310.9,231.5 | v349.1,193.29 349.5,192.89 v349.5,170.94 349.1,170.94 349.1,157.12 v348.69,156.72
  Route15 0.203: v310.49,244.5 309.68,245.31 309.68,246.94 A12.K2 | v310.9,231.5 319.43,222.96 319.84,222.96 321.06,221.74 321.06,221.34 v349.1,193.29 | v408.43,157.12 423.47,142.09 423.47,139.24 439.32,123.39 439.32,121.36 C02.F1
  Bottom 0.203: v349.5,170.94 348.69,170.13 336.91,170.13 335.69,171.35 B10.M2 | v408.43,157.12 366.57,157.12 366.17,157.53 357.23,157.53 356.82,157.94 355.6,157.94 353.97,156.31 351.94,156.31 351.54,156.72 v348.69,156.72
KEY_EX+DP\  (via drill 0.61)
  Top 0.203: v453.14,112.83 452.32,112.01 452.32,109.98 453.95,108.36 453.95,69.75 453.54,69.34 453.54,65.28 454.36,64.47 454.36,29.92 455.17,29.11 D01.P1
  Bottom 0.203: 453.95,29.92 454.36,29.92 455.17,29.11 D01.P1 | 453.95,29.92 445.82,29.92 442.57,33.17 436.47,33.17 433.22,36.42 419.4,36.42 418.19,35.2 D04.M1 | 453.95,29.92 453.95,40.49 445.41,49.02 443.38,49.02 443.38,53.49 D02.E1 | v453.14,112.83 436.88,112.83 436.88,116.89 C02.H2
KEY_EX\  (via drill 0.61)
  Top 0.203: v447.85,122.99 447.45,122.58 447.45,99.42 v445.82,97.79 | v452.73,68.12 451.1,66.5 451.1,18.14 449.48,16.51 D01.U2
  Route15 0.203: v445.82,97.79 442.98,94.94 v455.17,82.75
  Bottom 0.203: v447.85,122.99 443.79,122.99 443.38,123.39 C02.E1 | v455.17,82.75 455.17,69.75 453.95,69.75 452.73,68.53 v452.73,68.12
KEY_LA  (via drill 0.61)
  Top 0.203: v282.04,179.48 282.45,179.07 282.45,173.38 281.23,172.16 v281.23,171.75 | v235.71,122.17 235.31,121.77 235.31,41.3 241.4,35.2 | 241.4,35.2 242.62,33.98 242.62,32.36 D17.N2 | v340.16,3.91 299.52,3.91 v299.52,7.98 | v245.87,7.57 241.4,12.04 241.4,35.2
  Route2 0.203: v282.04,179.48 282.45,179.48 287.73,184.76 287.73,185.17 293.42,190.86 293.42,192.89 B13.D2 | v281.23,171.75 277.98,168.5 277.98,167.28 260.5,149.81 260.5,148.18 241.4,129.08 241.4,127.86 v235.71,122.17 | v429.56,62.84 371.04,4.32 355.19,4.32 354.38,3.5 343,3.5 341.38,5.13 v340.16,3.91
  Bottom 0.203: D17.N2 243.43,32.36 245.47,34.39 D17.M2 | v429.56,62.84 430.78,62.84 431.6,62.03 438.51,62.03 439.32,62.84 D02.B1 | v299.52,7.98 298.7,7.16 262.13,7.16 261.72,7.57 v245.87,7.57
KEY_LA+EX+DP  (via drill 0.61)
  Top 0.203: 352.75,49.02 352.35,49.43 352.35,57.56 351.13,58.78 v350.72,58.78 | 352.75,49.02 353.57,48.21 D09.H1 | v308.05,281.48 298.7,272.14 298.7,245.72 299.52,244.91 A13.L1 | v422.25,281.08 422.25,231.9 425.91,228.24 425.91,203.05 428.35,200.61 428.35,130.3 425.91,127.86 425.91,118.11 v429.97,114.05 | v354.38,37.24 352.75,38.86 352.75,49.02
  Route15 0.203: v419,59.59 419,62.43 419.4,62.84 419.4,67.72 v421.03,69.34 | v271.48,96.57 275.95,96.57 292.61,79.91 292.61,79.1 293.01,78.69 295.05,78.69 297.08,80.72 301.14,76.66 301.14,70.56 303.58,68.12 303.99,68.12 323.49,48.62 323.49,48.21 323.9,47.8 325.12,47.8 333.65,39.27 333.65,33.98 343.41,24.23 351.94,24.23 359.66,31.95 v354.38,37.24
  Bottom 0.203: v350.72,58.78 351.13,59.18 375.51,59.18 376.33,58.37 382.42,58.37 383.24,59.18 418.59,59.18 v419,59.59 | v421.03,69.34 421.84,70.16 452.32,70.16 454.36,72.19 454.36,109.17 442.16,109.17 441.76,108.76 440.54,108.76 439.73,109.58 438.51,109.58 437.29,110.79 C02.K2 436.07,111.61 432.41,111.61 v429.97,114.05 | v308.05,281.48 308.46,281.89 327.15,281.89 328.37,280.67 329.18,280.67 330,281.48 360.48,281.48 361.29,280.67 362.92,280.67 364.13,281.89 386.89,281.89 388.11,280.67 389.74,280.67 390.14,281.08 v422.25,281.08 | v271.48,96.57 274.73,99.82 288.54,99.82 289.76,98.6 C14.P1
KEY_LA+EX+DP\  (via drill 0.61)
  Top 0.203: v107.7,106.32 107.7,122.58 106.88,123.39 C28.E2
  Route2 0.203: v223.93,60 230.02,66.09 245.47,50.65 247.5,50.65 247.9,51.05 247.9,51.46 249.12,52.68 253.19,52.68 254.41,53.9 254.41,57.96 276.76,80.31 278.79,80.31 279.6,81.13 279.6,83.16 288.14,91.69 289.76,91.69 C14.S1
  Route15 0.203: v223.93,60 223.93,60.4 219.46,64.87 212.14,64.87 193.04,83.97 186.13,83.97 182.88,87.22 178,87.22 170.28,94.94 169.06,94.94 167.44,96.57 163.37,96.57 v158.5,101.45
  Bottom 0.203: v158.5,101.45 157.68,102.26 155.25,102.26 154.03,103.48 134.93,103.48 132.08,106.32 v107.7,106.32
KEY_LA\  (via drill 0.61)
  Top 0.203: v447.04,67.31 447.85,66.5 447.85,24.23 449.07,23.01 D01.S2 | v439.73,110.79 441.35,109.17 441.35,83.97 442.57,82.75 442.57,67.31 D02.A1
  Route2 0.203: C05.U2 399.08,86 400.71,86 405.99,91.29 405.99,95.35 413.71,103.07 418.59,103.07 419.81,104.29 421.03,104.29 429.16,112.42 431.19,112.42 432.82,114.05 C02.J2
  Bottom 0.203: D01.U1 455.17,16.51 455.17,20.98 450.7,20.98 449.88,21.79 D01.S2 | v447.04,67.31 443.38,67.31 D02.A1 | v439.73,110.79 438.1,112.42 435.66,112.42 434.04,114.05 C02.J2
KEY_PROTECT\  (via drill 0.61)
  Top 0.203: v453.14,111.61 453.95,112.42 453.95,115.27 453.54,115.67 453.54,120.14 454.36,120.95 454.36,271.73 455.17,272.54 A01.A1
  Route2 0.203: v455.17,109.58 455.98,108.76 455.98,107.54 453.95,105.51 453.95,82.75 455.17,81.53 455.17,68.12 447.45,60.4 447.45,56.34 438.1,46.99 438.1,46.18 437.69,45.77 437.69,40.49 432.41,35.2 440.94,26.67 440.94,18.14 440.13,17.32 440.13,13.26 D02.V1
  Route15 0.203: v455.17,109.58 v453.14,111.61
KEY_SS+I_REF  (via drill 0.61)
  Top 0.203: v360.88,38.46 362.1,39.68 362.1,53.9 v362.51,54.3
  Route2 0.203: v362.51,54.3 364.13,55.93 364.95,55.93 390.14,81.13 390.14,85.6 397.05,92.51 397.05,92.91 403.96,99.82 408.84,99.82 427.94,118.92 v427.94,119.33
  Bottom 0.203: v360.88,38.46 359.26,36.83 356.41,36.83 354.79,35.2 D09.M1 | v427.94,119.33 428.75,120.14 432.82,120.14 C02.F2
KEY_SS\  (via drill 0.61)
  Top 0.203: v433.22,98.2 433.22,98.6 434.85,100.23 434.85,117.7 435.66,118.52 435.66,122.99 436.07,123.39 C02.E2 | v453.14,78.28 453.54,77.88 453.54,70.16 450.7,67.31 450.7,19.36 447.85,16.51 447.85,12.45 446.63,11.23 444.6,11.23 444.6,13.66 445.82,14.88 445.82,18.54 D01.T2
  Route15 0.203: v453.14,78.28 v433.22,98.2
KEY_ST  (via drill 0.61)
  Top 0.203: v433.22,92.1 432,93.32 v432,123.39 | v309.27,81.94 308.46,81.13 308.46,72.59 312.12,68.94 312.12,64.47 312.52,64.06 D12.B1 | v313.74,98.2 314.15,98.6 314.15,146.56 v313.74,146.96 | v308.86,147.37 308.05,148.18 308.05,155.09 310.9,157.94 310.9,197.36 308.46,199.8 308.46,202.23 308.05,202.64 308.05,212.39 309.27,213.61 309.27,221.74 A12.U2 | v351.13,65.28 345.03,65.28 v345.03,70.97
  Route2 0.203: v309.27,81.94 305.61,78.28 304.8,78.28 302.36,80.72 303.58,81.94 303.58,82.75 304.39,83.57 304.39,88.85 v313.74,98.2 | v320.24,71.37 319.43,70.56 317.81,70.56 314.55,67.31 314.55,65.28 313.33,64.06 D12.B1
  Route15 0.203: v404.77,72.19 404.77,70.97 398.27,64.47 v397.46,65.28
  Bottom 0.203: v433.22,92.1 434.44,90.88 436.47,90.88 436.47,86.41 C02.U2 437.29,85.6 438.91,83.97 446.63,83.97 447.45,83.16 447.45,78.69 442.57,78.69 435.25,71.37 417.37,71.37 416.15,70.16 408.03,70.16 405.99,72.19 v404.77,72.19 | v432,123.39 438.51,129.9 442.16,129.9 C02.C1 | v313.74,146.96 313.33,147.37 v308.86,147.37 | v397.46,65.28 397.05,64.87 381.61,64.87 381.2,64.47 377.14,64.47 376.73,64.87 369.01,64.87 368.61,64.47 364.54,64.47 364.13,64.87 355.19,64.87 354.79,64.47 351.94,64.47 v351.13,65.28 | v345.03,70.97 344.63,71.37 v320.24,71.37
KEY_ST+EX+DP  (via drill 0.61)
  Route2 0.203: v303.58,77.47 301.95,79.1 301.95,86.41 302.36,86.82 302.36,88.44 316.59,102.67 316.99,102.67 319.84,105.51 319.02,106.32 318.21,106.32 316.99,105.1 316.59,105.1 C12.M1
  Route15 0.203: v303.58,77.47 303.58,77.06 309.27,71.37 309.27,70.56 310.08,69.75 310.49,69.75 310.9,69.34 310.9,68.53 v348.29,31.14
  Bottom 0.203: v348.29,31.14 349.1,30.33 412.5,30.33 413.71,31.55 D04.N1
KEY_ST\  (via drill 0.61)
  Top 0.203: v419,30.33 419,39.27 417.78,40.49 D04.K1 418.19,41.71 418.19,43.74 421.84,47.4 v421.84,62.03 | v449.48,120.14 447.85,118.52 v447.85,88.04
  Route2 0.203: v447.85,88.04 v421.84,62.03
  Route15 0.203: v449.48,120.14 444.19,125.42 444.19,130.71 443.38,131.52 443.38,135.99 C02.A1
  Bottom 0.203: D01.R1 451.92,25.04 446.63,25.04 D01.R2 445.41,25.86 444.6,26.67 422.66,26.67 v419,30.33
KEY_STOP  (via drill 0.61)
  Route2 0.203: v365.76,43.33 365.76,43.74 366.98,44.96 368.2,44.96 372.26,49.02 377.95,49.02 392.99,64.06 393.8,64.06 400.71,70.97 401.12,70.97 402.74,72.59 402.74,73.81 433.22,104.29 434.04,104.29 438.91,109.17 439.73,109.17 440.94,110.39 441.76,110.39 442.16,110.79 C02.K1
  Route15 0.203: v365.76,43.33 364.95,44.15 364.95,44.96 356.01,53.9 354.79,53.9 D09.E1
KEY_STOP\  (via drill 0.61)
  Top 0.203: v454.36,68.94 v454.36,116.08
  Route2 0.203: v455.17,42.93 447.85,35.61 447.85,33.58 446.63,32.36 D01.N2
  Bottom 0.203: v454.36,116.08 444.19,116.08 443.38,116.89 C02.H1 | v454.36,68.94 454.36,42.93 v455.17,42.93
L\_ENABLE  (via drill 0.61)
  Top 0.203: v314.55,204.27 314.55,185.57 315.37,184.76 B12.H1
  Route2 0.203: v314.55,204.27 314.55,202.23 315.77,201.02 317.4,202.64 317.4,203.45 322.68,208.74 323.49,208.74 333.25,218.49 333.25,220.52 334.47,221.74 A10.U2
L_ENABLE  (via drill 0.61)
  Top 0.203: v306.43,214.02 306.83,214.43 306.83,218.49 A12.V2 | v340.56,216.86 340.97,217.27 340.97,221.74 A10.U1
  Bottom 0.203: v306.43,214.02 309.27,216.86 v340.56,216.86
LEFT_SHIFT  (via drill 0.61)
  Top 0.203: v338.53,170.94 338.53,174.19 B10.L1 | v404.37,210.77 406.4,212.8 406.4,222.56 406.81,222.96 406.81,255.88 407.62,256.69 AB04.AF2
  Route2 0.203: v404.37,210.77 401.12,207.52 400.71,207.52 392.58,199.39 391.36,199.39 361.7,169.72 356.41,169.72 351.94,165.25 348.29,165.25 B09.P2
  Route15 0.203: v338.53,170.94 345.85,163.63 347.07,164.85 B09.P2
  Bottom 0.203: 381.2,258.32 371.45,258.32 370.64,257.5 AB07.AF2 | 381.2,258.32 382.02,257.5 AB06.AF2 | 381.2,258.32 393.8,258.32 394.61,257.5 AB05.AF2 395.83,257.5 398.68,257.5 399.49,258.32 406.4,258.32 | 406.4,258.32 407.21,257.5 AB04.AF2 | 406.4,258.32 419.4,258.32 420.22,257.5 AB03.AF2 421.44,257.5 423.88,257.5 424.69,258.32 432,258.32 432.82,257.5 AB02.AF2
LINK  (via drill 0.61)
  Top 0.203: v286.51,109.98 286.11,110.39 286.11,123.8 v287.32,125.02
  Route2 0.203: v286.51,109.98 284.89,108.36 281.63,108.36 C14.L2 | v287.32,125.02 298.3,135.99 298.3,139.24 318.21,159.16 | 318.21,159.16 320.24,161.19 320.24,162.81 321.87,164.44 B11.P2 | v340.56,214.02 340.56,213.61 339.75,212.8 339.75,205.08 335.69,201.02 335.69,199.39 331.22,194.92 330.81,194.92 325.53,189.64 325.53,189.23 321.87,185.57 321.46,185.57 321.06,185.17 321.06,181.1 319.43,179.48 319.43,177.85 313.74,172.16 313.74,171.35 311.3,168.91 311.3,166.06 318.21,159.16
  Route15 0.203: v340.56,214.02 342.6,216.05 342.6,222.96 341.38,224.18 341.38,227.84 A10.S1
LINK\  (via drill 0.61)
  Top 0.203: v337.72,201.83 337.31,202.23 337.31,218.08 337.72,218.49 A10.V1 | v346.25,274.17 346.25,251 349.1,248.16 349.1,240.84 348.69,240.44 348.69,236.78 350.32,235.15 350.32,233.12 349.5,232.31 v349.5,228.65
  Route2 0.203: v337.72,201.83 336.09,200.2 336.09,196.14 323.49,183.54 323.49,182.73 319.84,179.07 319.84,177.44 314.15,171.75 314.15,168.5 314.96,167.69 315.37,167.69 318.62,164.44 318.62,162.41 B11.R2 | v349.5,228.65 349.5,228.24 340.56,219.3 338.94,219.3 A10.V1
  Bottom 0.203: v346.25,274.17 346.66,274.57 366.98,274.57 367.39,274.17 369.82,274.17 371.04,275.39 450.7,275.39 450.7,269.7 455.17,265.23 455.57,265.23 455.57,261.16 A01.E1
LOCK  (via drill 0.61)
  Top 0.203: v251.16,43.74 251.16,12.85 254.81,12.85 D16.V2 | v254.41,47.4 254,47.8 254,94.94 251.16,97.79 v251.16,114.05
  Route2 0.203: v251.16,43.74 251.16,44.15 v254.41,47.4
  Bottom 0.203: v251.16,114.05 253.19,116.08 266.19,116.08 267.41,117.3 270.66,117.3 C15.H2
LOCK\  (via drill 0.61)
  Top 0.203: 294.23,86 293.83,86.41 293.83,88.44 C13.T2 | 294.23,86 295.45,86 295.45,90.07 296.67,91.29 C13.S2 | 275.95,79.5 275.95,83.57 273.51,86 273.51,106.32 274.32,107.14 C15.L1 | 275.95,79.5 275.95,42.11 269.85,36.02 269.85,24.23 263.75,18.14 263.75,14.48 262.53,13.26 D16.V1 | 294.23,86 291.8,83.57 v291.8,79.5 | 275.95,79.5 v273.51,79.5
  Bottom 0.203: v273.51,79.5 v291.8,79.5
MA00  (via drill 0.61)
  Top 0.203: v168.25,111.61 168.25,122.17 169.47,123.39 C23.E2 | v336.91,85.19 337.72,86 337.72,87.63 336.5,88.85 336.5,99.82 337.72,101.04 C10.N1 | v397.05,200.2 397.05,147.78 396.65,147.37 396.65,145.75 395.43,144.53 395.43,138.43 396.65,137.21 396.65,124.61 v396.24,124.21
  Route2 0.203: v310.49,57.56 310.49,59.18 334.87,83.57 334.87,83.97 335.28,84.38 336.09,84.38 v336.91,85.19 | v365.76,231.09 372.67,238 372.67,240.84 AB07.AM2 | v396.24,124.21 396.24,123.8 390.96,118.52 390.96,116.48 390.14,115.67 390.14,113.64 364.95,88.44 364.95,88.04 358.04,81.13 351.94,81.13 v349.91,79.1
  Route15 0.203: v258.47,107.14 293.01,72.59 293.01,72.19 294.64,70.56 295.45,70.56 295.86,70.16 297.49,70.16 310.08,57.56 v310.49,57.56 | v365.76,231.09 366.17,231.09 383.24,214.02 383.24,213.21 387.3,209.14 388.11,209.14 v397.05,200.2 | v349.91,79.1 345.03,83.97 338.53,83.97 337.31,85.19 v336.91,85.19
  Bottom 0.203: v168.25,111.61 169.06,112.42 223.11,112.42 225.55,109.98 255.63,109.98 v258.47,107.14
MA00\  (via drill 0.61)
  Route2 0.203: v198.73,124.21 222.3,147.78 224.33,147.78 250.75,174.19 250.75,174.6 252.78,176.63 253.19,176.63 v280.42,203.86 v298.7,222.15 | v328.78,239.62 323.49,239.62 v307.24,223.37
  Route15 0.203: v39.01,253.03 38.2,252.22 38.2,242.47 60.55,220.12 60.55,219.3 130.05,149.81 130.05,149 153.21,125.83 154.84,125.83 156.46,124.21 C24.E2
  Bottom 0.203: A01.M2 448.67,240.84 447.85,240.03 380.8,240.03 379.98,240.84 AB07.AM1 378.76,240.84 377.95,240.03 350.72,240.03 349.91,239.22 346.66,239.22 345.85,240.03 329.18,240.03 v328.78,239.62 | v39.01,253.03 38.61,252.63 26.82,252.63 25.2,251 21.13,251 A35.J1 | v280.42,203.86 281.23,204.67 284.89,204.67 286.11,203.45 289.76,203.45 B14.A1 | v198.73,124.21 197.1,122.58 158.5,122.58 157.68,123.39 C24.E2 | v307.24,223.37 306.83,223.77 300.33,223.77 v298.7,222.15
MA01  (via drill 0.61)
  Top 0.203: v154.43,109.58 154.84,109.98 154.84,113.23 156.87,115.27 156.87,116.89 C24.H2 | v401.12,214.83 402.74,213.21 402.74,206.7 400.3,204.27 400.3,163.63 399.49,162.81 399.49,159.97 400.3,159.16 400.3,152.65 403.15,149.81 403.15,120.14 v401.12,118.11
  Route2 0.203: v316.59,82.35 315.37,81.13 315.37,79.1 314.96,78.69 316.59,77.06 317.4,77.06 318.62,78.28 321.46,78.28 324.31,81.13 324.31,83.57 338.94,98.2 340.56,98.2 C10.P1 341.78,99.01 343,100.23 345.03,100.23 347.07,102.26 v347.47,102.26 | v401.12,118.11 391.36,108.36 390.96,108.36 386.89,104.29 386.89,103.89 376.73,93.73 373.48,93.73 373.07,93.32 372.26,93.32 v367.39,88.44
  Route15 0.203: v302.77,82.75 301.95,82.75 294.64,90.07 290.17,90.07 281.63,98.6 279.6,98.6 272.29,105.92 v268.63,105.92 | v401.12,214.83 401.12,215.24 382.02,234.34 382.02,235.56 381.61,235.97 381.61,236.78 379.98,238.4 379.17,238.4 373.48,244.09 370.64,244.09 AB07.AL2 | v367.39,88.44 366.17,88.44 361.29,93.32 357.23,93.32 351.13,99.42 350.32,99.42 v347.47,102.26
  Bottom 0.203: C24.H2 157.68,116.89 158.5,116.08 167.84,116.08 169.06,117.3 C23.H2 | v316.59,82.35 315.37,83.57 313.74,83.57 313.33,83.97 304.8,83.97 303.58,82.75 v302.77,82.75 | v268.63,105.92 268.22,106.32 233.68,106.32 230.43,109.58 175.97,109.58 175.56,109.98 156.46,109.98 156.06,109.58 v154.43,109.58
MA01\  (via drill 0.61)
  Top 0.203: v282.04,201.42 282.45,201.83 282.45,223.37 282.04,223.77 282.04,224.59 282.45,224.99 282.45,239.22 281.23,240.44 v281.23,241.66
  Route15 0.203: v281.23,241.66 284.07,244.5 v283.67,244.91
  Bottom 0.203: v282.04,201.42 282.45,201.02 286.51,201.02 286.92,200.61 B14.B1 | A35.L1 21.13,244.91 21.95,245.72 76,245.72 76.4,246.13 196.29,246.13 196.7,245.72 214.17,245.72 216.61,243.28 233.68,243.28 236.12,245.72 282.45,245.72 283.26,244.91 v283.67,244.91 285.29,243.28 296.27,243.28 298.7,245.72 374.7,245.72 375.51,244.91 AB07.AL1 376.73,244.91 379.17,244.91 380.39,246.13 451.92,246.13 451.92,250.19 A01.J1
MA02  (via drill 0.61)
  Top 0.203: v337.31,91.29 337.31,94.13 337.72,94.54 C10.R1 | v358.85,133.15 358.44,132.74 358.44,111.61 v358.04,111.2
  Route2 0.203: v337.31,91.29 337.31,90.07 331.62,84.38 330.81,84.38 v305.61,59.18 | v416.56,199.8 408.84,192.07 408.84,190.45 403.56,185.17 403.56,179.48 389.33,165.25 388.93,165.25 369.42,145.75 369.42,145.34 363.73,139.65 363.73,138.02 v358.85,133.15 | v358.04,111.2 343.41,96.57 340.16,96.57 338.94,95.35 C10.R1
  Route15 0.203: v232.46,56.74 219.86,69.34 210.11,69.34 206.86,72.59 206.86,78.28 203.61,81.53 203.61,85.6 170.28,118.92 169.06,118.92 167.44,120.55 C23.F2 | v416.56,199.8 412.09,204.27 412.09,206.3 403.56,214.83 403.56,221.74 399.9,225.4 399.9,229.06 387.71,241.25 386.49,241.25 AB06.AM2
  Bottom 0.203: v305.61,59.18 290.98,59.18 286.92,55.12 257.25,55.12 256.85,54.71 253.59,54.71 252.37,55.93 233.27,55.93 v232.46,56.74 | C24.F2 154.43,120.14 155.25,119.33 165.41,119.33 166.22,120.14 C23.F2
MA02\  (via drill 0.61)
  Top 0.203: v345.03,214.83 347.07,216.86 v347.07,219.3 | v388.52,223.37 390.96,225.81 390.96,239.22 | 390.96,239.22 390.96,240.03 391.77,240.84 AB06.AM1 | 390.96,239.22 v392.58,239.22 | v290.17,200.61 290.17,197.36 B14.C1
  Route2 0.203: v310.08,215.65 298.3,203.86 298.3,202.64 293.01,197.36 290.98,197.36 B14.C1
  Route15 0.203: v33.73,272.95 36.58,270.1 19.51,253.03 19.51,243.69 20.32,242.88 20.32,238.81 A35.N1 | v218.24,278.23 254.81,241.66 255.22,241.66 257.25,239.62 257.25,238.4 275.95,219.71 275.95,215.65 276.35,215.24 276.35,214.43 v290.17,200.61
  Bottom 0.203: v310.08,215.65 313.74,215.65 314.15,215.24 323.09,215.24 323.9,214.43 339.75,214.43 340.16,214.83 v345.03,214.83 | v347.07,219.3 348.69,217.68 359.26,217.68 365.35,223.77 388.11,223.77 v388.52,223.37 | v392.58,239.22 392.99,239.62 449.07,239.62 449.07,235.56 A01.P2 | v33.73,272.95 36.17,275.39 101.19,275.39 101.6,275.79 154.43,275.79 156.06,277.42 174.35,277.42 175.16,278.23 v218.24,278.23
MA03  (via drill 0.61)
  Top 0.203: D19.E2 221.08,54.71 222.3,55.93 v222.3,57.56 222.3,57.96 222.3,75.84 203.61,94.54 203.61,195.73 v204.01,196.14 | v320.24,273.76 318.62,275.39 318.62,277.83 314.55,281.89 310.08,281.89 v310.08,281.08
  Route2 0.203: v288.14,60 296.27,68.12 297.89,68.12 301.55,71.78 302.36,71.78 310.9,80.31 313.33,80.31 316.18,83.16 316.99,83.16 320.24,86.41 321.06,86.41 327.96,93.32 329.59,93.32 331.22,94.94 C10.R2 | v310.08,281.08 308.46,282.7 302.77,282.7 301.95,281.89 294.64,281.89 293.42,280.67 289.76,280.67 282.45,273.36 281.63,273.36 216.21,207.92 215.8,207.92 v204.01,196.14
  Route15 0.203: v355.19,275.39 382.02,248.56 382.02,244.91 AB06.AL2
  Bottom 0.203: v222.3,57.56 223.52,58.78 286.92,58.78 v288.14,60 | v355.19,275.39 354.38,276.2 336.5,276.2 334.87,274.57 321.06,274.57 v320.24,273.76
MA03\  (via drill 0.61)
  Top 0.203: v222.71,129.9 222.71,80.72 228.4,75.03 228.4,54.3 232.87,54.3 D18.E2 | v387.71,279.45 387.71,245.72 388.52,244.91 AB06.AL1 | v275.13,280.67 270.26,275.79 v270.26,235.97 | v265.79,231.5 263.75,229.46 263.75,216.86 266.6,214.02 266.6,196.14 v265.79,195.33
  Route2 0.203: v222.71,129.9 222.71,130.3 239.78,147.37 239.78,148.59 v241,149.81 267,175.82 267.41,175.82 267.82,176.22 267.82,177.04 278.38,187.6 279.2,187.6 283.26,191.67 285.29,191.67 286.92,193.29 B14.D1 | v265.79,231.5 v270.26,235.97
  Route15 0.203: v401.12,229.46 394.61,235.97 393.8,235.97 384.86,244.91 384.45,244.91 382.83,246.53 382.83,246.94 382.42,247.34 384.05,248.97 386.49,248.97 388.52,246.94 388.52,244.91 AB06.AL1 | v102.82,146.56 87.78,161.59 87.38,161.59 66.65,182.32 66.65,183.13 43.08,206.7 41.86,206.7 41.45,207.11 40.64,207.11 39.01,208.74 39.01,209.14 20.73,227.43 20.73,231.09 A35.R1
  Bottom 0.203: v401.12,229.46 401.52,229.87 447.85,229.87 448.67,229.06 A01.S2 | v102.82,146.56 117.86,146.56 119.48,148.18 121.11,148.18 121.51,147.78 145.9,147.78 147.52,146.15 165.81,146.15 167.03,147.37 176.78,147.37 177.19,147.78 180.85,147.78 182.07,146.56 232.05,146.56 233.27,147.78 237.74,147.78 239.78,149.81 v241,149.81 | v387.71,279.45 386.08,281.08 364.95,281.08 363.73,279.86 360.48,279.86 359.66,280.67 330.81,280.67 330,279.86 327.56,279.86 326.34,281.08 312.52,281.08 311.71,280.26 275.54,280.26 v275.13,280.67 | v265.79,195.33 266.19,194.92 284.48,194.92 285.29,194.11 286.92,194.11 B14.D1
MA04  (via drill 0.61)
  Top 0.203: v417.37,220.12 418.59,218.9 418.59,206.3 415.75,203.45 415.75,190.86 412.9,188.01 412.9,147.37 409.65,144.12 v409.65,128.27 | v356.82,111.61 357.23,111.2 357.23,109.58 358.85,107.95 358.85,104.29 360.07,103.07 v360.48,103.07 | v352.35,102.26 352.75,101.85 352.75,99.82 351.13,98.2 v350.32,98.2
  Route2 0.203: D18.H2 234.09,47.8 235.71,49.43 262.53,49.43 270.26,57.15 271.88,57.15 273.91,59.18 291.39,59.18 301.55,69.34 308.05,69.34 308.86,70.16 315.77,70.16 330.4,84.78 330.4,85.6 334.87,90.07 334.87,91.29 C10.S2 335.69,92.51 336.91,93.73 345.03,93.73 349.5,98.2 v350.32,98.2 | v409.65,128.27 409.65,125.42 v395.83,111.61
  Route15 0.203: v417.37,220.12 399.08,238.4 399.08,240.84 AB05.AM2
  Bottom 0.203: D19.H2 221.08,46.99 221.89,46.18 232.05,46.18 232.87,46.99 D18.H2 | v395.83,111.61 394.21,109.98 382.42,109.98 379.98,112.42 377.95,112.42 375.51,109.98 357.63,109.98 356.82,110.79 v356.82,111.61 | v360.48,103.07 360.07,103.48 358.85,103.48 358.44,103.89 356.01,103.89 354.38,102.26 v352.35,102.26
MA04\  (via drill 0.61)
  Top 0.203: v405.99,223.37 405.99,240.03 405.18,240.84 AB05.AM1 405.18,242.06 406.4,243.28 406.4,264.41 406.81,264.82 v406.81,276.2 | v99.57,217.27 104.04,212.8 104.04,208.74 104.85,207.92 104.85,189.64 106.48,188.01 v106.48,187.2 | v234.49,277.01 234.49,251 233.68,250.19 233.68,249.38 234.49,248.56 234.49,240.44 v233.27,239.22 | v227.99,236.78 225.96,236.78 225.96,235.97 222.71,232.72 222.71,217.27 223.52,216.46 223.52,201.83 222.71,201.02 v222.71,192.48
  Route15 0.203: v23.16,216.86 21.54,218.49 21.13,218.49 A35.V1
  Bottom 0.203: v405.99,223.37 406.4,223.77 447.45,223.77 448.67,222.56 A01.U2 | 168.25,192.48 167.44,193.29 B23.D2 | 168.25,192.48 v222.71,192.48 277.57,192.48 278.38,193.29 280.42,193.29 B14.D2 | v23.16,216.86 99.16,216.86 v99.57,217.27 | v106.48,187.2 107.7,185.98 136.96,185.98 140.21,189.23 152.4,189.23 155.65,192.48 168.25,192.48 | v406.81,276.2 406.4,275.79 368.2,275.79 366.98,277.01 357.63,277.01 356.82,277.83 334.47,277.83 332.84,276.2 316.99,276.2 316.59,275.79 306.43,275.79 304.8,277.42 286.51,277.42 286.11,277.01 256.03,277.01 255.22,277.83 236.12,277.83 235.31,277.01 v234.49,277.01 | v233.27,239.22 230.84,236.78 v227.99,236.78
MA05  (via drill 0.61)
  Top 0.203: v202.39,219.71 199.95,217.27 199.95,197.36 193.45,190.86 193.45,84.38 216.21,61.62 216.21,52.27 217.02,51.46 D19.F2
  Route2 0.203: v379.58,239.22 383.64,243.28 389.74,243.28 390.96,244.5 394.61,244.5 AB05.AL2 | v315.37,279.86 312.12,283.11 302.36,283.11 301.55,282.3 282.04,282.3 280.82,281.08 276.76,281.08 275.54,279.86 274.32,279.86 273.51,279.04 264.57,279.04 262.13,276.61 259.28,276.61 v202.39,219.71
  Route15 0.203: v379.58,239.22 379.17,239.22 373.89,244.5 371.86,244.5 351.54,264.82 340.56,264.82 333.25,272.14 331.62,272.14 329.18,274.57 320.65,274.57 v315.37,279.86
  Bottom 0.203: D19.F2 218.24,50.65 219.46,49.43 228.8,49.43 229.62,50.24 D18.F2
MA05\  (via drill 0.61)
  Top 0.203: v402.74,227.43 403.15,227.84 403.15,242.47 401.93,243.69 AB05.AL1 | v173.53,189.23 173.13,189.64 173.13,192.89 B23.D1
  Route2 0.203: v241.81,277.01 219.46,254.66 219.46,244.5 188.98,214.02 188.98,211.58 174.75,197.36 174.75,195.33 173.53,194.11 B23.D1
